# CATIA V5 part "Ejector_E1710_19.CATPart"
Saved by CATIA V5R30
Part number: Vyhazovac_4x160_6
Nomenclature: E1710/4x160
Description: MEUSBURGER
Property "Material": "1.221"
Publications: "__DrillHole", "Base"
Bounding box of the stored display mesh (mm): x -3.996 to 3.996, y -3.999 to 3.999, z 0 to 152
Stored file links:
  E:\Bakalarka\Model\Forma_v7\Ejector_E1710_19.CATPart
  E:\dev\MoldDesign\intel_a\startup\components\MoldCatalog\Ejector\Meusburger\Ejector_E1710\TableE1710.txt
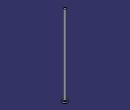
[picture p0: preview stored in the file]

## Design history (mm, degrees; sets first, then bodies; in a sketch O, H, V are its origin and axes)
Parameters
  Ref = "E1710/4x160" {design table}
  D1 = 4 mm {design table}
  D3 = 8 mm {design table}
  L = 160 mm {design table}
  L3 = 3 mm {design table}
  R = 0.3 mm {design table}
  k_d3 = 9 mm {design table}
  k_d1 = 4.2 mm {design table}
  k_F = 0.3 mm {design table}
  kl = 17 mm {design table}
  Mat = "1.221" {design table}
  HeatTreat = "ISO6751" {design table}
  Offset_Parting = 10 mm
  Anti_Rotation = "Normal"
  Anti_Rotation_D = 2.3 mm
  Anti_Rotation_D_Icut = 2.3 mm
  Add_Length_L = 0.8377 mm
  Add_Length_D3 = 0 mm
  SupplierRef = "Meusburger 2017"
  BmpRef = "F_MldEjectorD1"
  DrillHole_Length = 225 mm
  ValidationTest = false
  Anti_Rotation_D_min = 2.3 mm {= OffSet_D1 /2}
  Anti_Rotation_D_max = 3.925 mm {= D3/2-0.075mm}
  Anti_Rotation_D_ref = 2.3 mm {= Anti_Rotation_D}
  Anti_Rotation_D_Icut_ref = 2.3 mm {= Anti_Rotation_D_Icut}
  Anti_Rotation_Ref_Icut = 2.3246 mm
  Offset_L = 20 mm
  D = 4 mm {= D1}
  OffSet_D1 = 4.6 mm {= D1+2*R}
  OffSet_D3 = 9 mm {= D3+1mm}
  XG_Split = 113.5 mm
  YG_Split = 54.5 mm
  ZG_Split = -198 mm
  DirX_Split = 0 mm
  DirY_Split = 0 mm
  DirZ_Split = 1 mm
Set1 "BaseBody"
  Point1 "Base": (0, 0, 0)
  Plane1: type Offset, RefPlane xy-plane, Offset 225 {= DrillHole_Length}, reversed
  Sketch1 "Sketch.2" on xy-plane, origin (0, 0, 0), H (1, 0, 0), V (0, 1, 0)
    point P1 (-0.46, 1.1623)
    point P2 (0.46, 1.1623)
    construction line L1 (-0.46, 1.1623) -> (0.46, 1.1623)
    point P3 (0.46, -1.1623)
    line L2 (0.46, -1.1623) -> (0.46, 1.1623)
    point P4 (-0.46, -1.1623)
    construction line L3 (0.46, -1.1623) -> (-0.46, -1.1623)
    line L4 (-0.46, 1.1623) -> (-0.46, -1.1623)
    point P5 (-0.21, 1.1623)
    arc A1 centre (-0.21, 1.1623) radius 0.25 from (-0.21, 1.4123) to (-0.46, 1.1623) ccw
    point P7 (0.21, 1.1623)
    point P8 (0.21, 1.4123)
    arc A2 centre (0.21, 1.1623) radius 0.25 from (0.46, 1.1623) to (0.21, 1.4123) ccw
    line L5 (-0.21, 1.4123) -> (0.21, 1.4123)
    point P9 (-0.46, -1.1623)
    arc A3 centre (-0.21, -1.1623) radius 0.25 from (-0.46, -1.1623) to (-0.21, -1.4123) ccw
    point P11 (0.21, -1.4123)
    line L6 (-0.21, -1.4123) -> (0.21, -1.4123)
    point P12 (0.46, -1.1623)
    arc A4 centre (0.21, -1.1623) radius 0.25 from (0.21, -1.4123) to (0.46, -1.1623) ccw
    point P14 (-0.46, 1.1623)
    point P15 (-0.46, -1.1623)
    point P16 (0.46, 1.1623)
    point P17 (0.46, -1.1623)
    reference projected circle E1 centre (0, 0) radius 1.25 from edge [face of Shaft1 from Sketch2.L3 | face of Shaft1 from Sketch2.L4]
    reference projected circle E2 centre (0, 0) radius 1.25 from edge [face of Shaft1 from Sketch2.L3 | face of Shaft1 from Sketch2.L4]
    reference projected circle E3 centre (0, 0) radius 1.25 from edge [face of Shaft1 from Sketch2.L3 | face of Shaft1 from Sketch2.L4]
    reference projected circle E4 centre (0, 0) radius 1.25 from edge [face of Shaft1 from Sketch2.L3 | face of Shaft1 from Sketch2.L4]
    point P18 (-0.46, -1.1623)
    point P19 (-0.21, -1.4123)
    point P20 (0.21, -1.4123)
    point P21 (0.46, -1.1623)
    point P22 (-0.21, -1.4123)
    point P23 (0.21, -1.4123)
    distance P14 P15 = 2.3246 (reference)
    distance P16 P17 = 2.3246 (reference)
    distance L1 P14 = 0 (reference)
    radius A1 = 2
    distance L4 V = 2.31
    distance L2 V = 3.935
    distance L5 L6 = 8
    horizontal: L1 H, L3 H, L5 H
    vertical: L2 V, L4 V
    coincidence: P5 L1, P7 L1, P3 P12, P14 L4, P15 L4, P16 L2, P17 L2, P14 E1, P15 E2, P16 E3, P17 E4, P3 P21, P4 P18, P20 P23, P19 P22
    tangency: A1 L4, A2 L2, A2 L5, A1 L5
    symmetry: P1 P9 H, A1 A3 H, P8 P11 H, L5 L6 H, P2 P12 H, A2 A4 H
  DatumSurface1
Body1 "PartBody" (main body)
  Sketch2 "Sketch.1" on zx-plane, origin (0, 0, 0), H (-1, 0, 0), V (0, 0, 1)
    point P1 (0, 160)
    line L1 (2, 160) -> (0, 160)
    line L2 (2, 3) -> (2, 160)
    line L3 (4, 3) -> (2, 3)
    line L4 (4, 0) -> (4, 3)
    point P5 (0, 0)
    line L5 (0, 0) -> (4, 0)
    point P6 (0, 160)
    axis line L6 (0, 160) -> (0, 0)
    point P7 (0, 0)
    point P8 (2, 3)
    point P9 (2, 3)
    line L7 (0, 160) -> (0, 0)
    distance L5 L3 = 3 {= L3}
    distance L5 L1 = 160 {= L}
    distance L2 L6 = 2 {= D1 /2}
    distance L4 L6 = 4 {= D3 /2}
    coincidence: L6 P5, P1 L6, L5 H, L6 V, P7 O, P6 P1, P8 P9
    vertical: L2 V, L7 V
    horizontal: L1 H
  Shaft1 "Shaft.1": profile Sketch2, axis Sketch2.L6, angle 360
  Pocket1 "Pocket.1": profile Sketch1, direction (0, 0, 1), length 4, outer side, deactivated
  Pocket2 "Pocket.2": profile Sketch1, direction (0, 0, 1), length 4, outer side, deactivated
  Fillet1: radius 0.3 {= R}, on edge [face of Shaft1 from Sketch2.L2 | face of Shaft1 from Sketch2.L3]
  Pocket3: profile face of Shaft1 from Sketch2.L1, direction along face of Shaft1 from Sketch2.L1 reversed, up to face of DatumSurface1
Body2 "__DrillHole"
  Sketch3 "Sketch.3" on face of Shaft1, origin (0, 0, 0), H (1, 0, 0), V (0, -1, 0)
    point P1 (0, 0)
    reference projected point E1 (0, 0) from Point1
    coincidence: E1 P1
  Hole1 "Hole.1": placed by Sketch3, at (0, 0, 0) direction (0, 0, 1), diameter 4.6 {= OffSet_D1}, depth 140 {= L-Offset_L}
  Sketch4 "Sketch.4" on face of Shaft1, origin (0, 0, 0), H (1, 0, 0), V (0, -1, 0)
    point P1 (0, 0)
    reference projected point E1 (0, 0) from Point1
    coincidence: E1 P1
  Hole2 "Hole.2": placed by Sketch4, at (0, 0, 0) direction (0, 0, 1), diameter 4 {= D1}, depth 160 {= L}
  Sketch5 "Sketch.5" on face of Shaft1 from Sketch2.L3, origin (0, 0, 3), H (1, 0, 0), V (0, 1, 0)
    point P1 (0, 0)
    reference projected point E1 (0, 0) from Point1
    coincidence: E1 P1
  Hole3 "Hole.3": placed by Sketch5, at (0, 0, 3) direction (0, 0, -1), diameter 9 {= OffSet_D3}, depth 228 {= L3 +DrillHole_Length}
  Chamfer1: length 0.3 {= k_F}, angle 45, on edge [face of Hole1 | face of Hole3]
  Body3 "__Body.1"
    Pocket4 "Pocket.3": profile Sketch1, direction (0, 0, -1), length 225, opposite side length 3, deactivated
  Assemble1: tool Body3
  Chamfer2: length 0.3 {= k_F}, angle 45, on edge [start face of Pocket4 | face of Hole1], deactivated
  Body4 "__Body.2"
    Pocket5 "Pocket.4": profile Sketch1, direction (0, 0, -1), length 225, opposite side length 3, deactivated
  Assemble2: tool Body4
  Chamfer3: length 0.3 {= k_F}, angle 45, on edge [start face of Pocket5 | face of Hole1], deactivated
Relations
  design table "TableE1710", configuration 187, drives Ref, D1, D3, L, L3, R, k_d3, k_d1, k_F, kl, Mat, HeatTreat
  Offset_L = 20mm (deactivated)
  rule "Cut_Head_rule":
    let sketch_cut (length)
    let PartBody_Pocket_Sketch (Boolean)
    let I_PartBody_Pocket (Boolean)
    let D_PartBody_Pocket (Boolean)
    let N_DrillHole_Hole (Boolean)
    let N_DrillHole_Hole_Sketch (Boolean)
    let I_DrillHole_Pocket (Boolean)
    let D_DrillHole_Pocket (Boolean)
    /* --------------------------------------------------------------------------------------*/
    if Anti_Rotation =="Normal"
    {
    	sketch_cut=Anti_Rotation_D_max
    	PartBody_Pocket_Sketch = false
    	I_PartBody_Pocket = false
    	D_PartBody_Pocket = false
    	N_DrillHole_Hole = true
    	N_DrillHole_Hole_Sketch = true
    	I_DrillHole_Pocket = false
    	D_DrillHole_Pocket = false
    	Chamfer1.Activity= true
    	Chamfer2.Activity= false
    	Chamfer3.Activity= false
    }
    if Anti_Rotation == "I_Cut"
    {
    	sketch_cut=Anti_Rotation_D_Icut_ref
    	PartBody_Pocket_Sketch = true
    	I_PartBody_Pocket = true
    	D_PartBody_Pocket = false
    	N_DrillHole_Hole = false
    	N_DrillHole_Hole_Sketch = false
    	I_DrillHole_Pocket = true
    	D_DrillHole_Pocket = false
    	Chamfer1.Activity= false
    	Chamfer2.Activity= true
    	Chamfer3.Activity= false
    }
    if Anti_Rotation =="D_Cut"
    {
    	sketch_cut=Anti_Rotation_D_max
    	PartBody_Pocket_Sketch = true
    	I_PartBody_Pocket = false
    	D_PartBody_Pocket = true
    	N_DrillHole_Hole = false
    	N_DrillHole_Hole_Sketch = false
    	I_DrillHole_Pocket = false
    	D_DrillHole_Pocket = true
    	Chamfer1.Activity= false
    	Chamfer2.Activity= false
    	Chamfer3.Activity= true
    }
    /* --------------------------------------------------------------------------------------*/
    Sketch1.distance(L2 V) = sketch_cut+0.01mm
    Sketch1.distance(L4 V) =Anti_Rotation_D_ref+0.01mm
    Sketch1.radius(A1) =D/2
    Pocket4.FirstLimit.Depth = DrillHole_Length
    Pocket5.FirstLimit.Depth = DrillHole_Length
    Pocket1.FirstLimit.Depth = L3+1mm
    Pocket2.FirstLimit.Depth = L3+1mm
    Pocket4.SecondLimit.Depth = L3
    Pocket5.SecondLimit.Depth =L3
    Pocket1.Activity = I_PartBody_Pocket
    Pocket2.Activity = D_PartBody_Pocket
    Sketch1.Activity =PartBody_Pocket_Sketch
    Hole3.Activity= N_DrillHole_Hole
    Sketch5.Activity = N_DrillHole_Hole_Sketch
    Pocket4.Activity = I_DrillHole_Pocket
    Pocket5.Activity  = D_DrillHole_Pocket
  rule "Anti_Rotation_Icut_constrain":
    let Ref1(length)
    let Ref2(length)
    let Ref3(length)
    let Diam1(length)
    let Diam2(length)
    let Add_Length_Lmin (length)
    Ref1=Sketch1.distance(P14 P15)
    Ref2=Sketch1.distance(P16 P17)
    Diam1=D
    Diam2=D3
    /* --------------------------------------------------------------------*/
    if Ref1 >Ref2
    	Anti_Rotation_Ref_Icut = Ref1
    else
    	Anti_Rotation_Ref_Icut  =Ref2
    Add_Length_D3 .InferiorRange=Anti_Rotation_Ref_Icut /2+Diam1/2 -Diam2/2
    if Add_Length_D3 .InferiorRange<0mm
    	Add_Length_D3 .InferiorRange=0mm
    if ValidationTest == "true"
    	Ref3   = 2*Add_Length_L +Anti_Rotation_Ref_Icut  +2*Diam1/2
    else
    	Ref3  =Diam2+2*Add_Length_D3
    if Ref3 <Diam2
    {
    	Ref3 =Diam2
    }
    /* --------------------------------------------------------------------*/
    Sketch1.distance(L5 L6) = Ref3
    Add_Length_L .InferiorRange=Diam2/2-Anti_Rotation_Ref_Icut/2-Diam1/2
    Add_Length_Lmin=Diam2/2-Anti_Rotation_Ref_Icut/2-Diam1/2
    if Add_Length_Lmin<0mm
    	Add_Length_L .InferiorRange=0mm
    else
    	Add_Length_L .InferiorRange=Add_Length_Lmin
